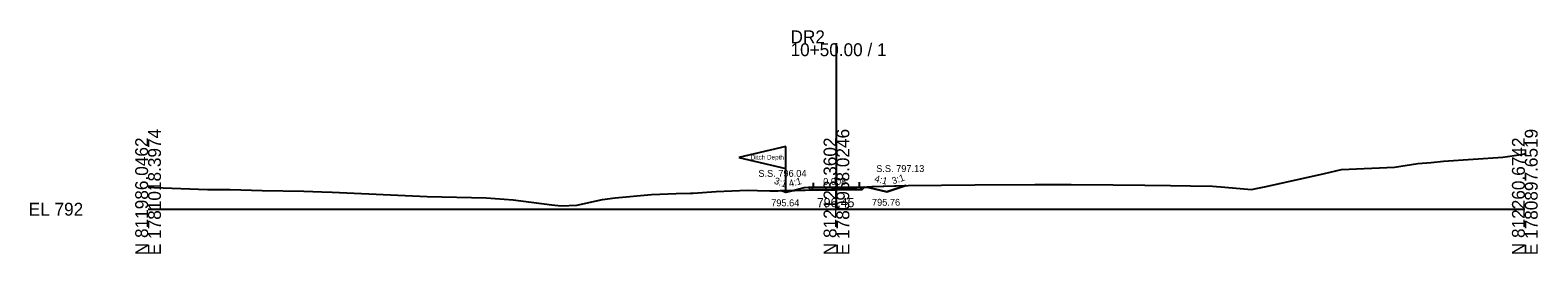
# Model space of a CAD drawing. Extents: x -26 to 303, y -10 to 2560.
# Drawn here: x -25.7 to 302.8, y 990.3 to 1038.9 of the extents above; entities that cross this region are included whole.
import ezdxf

# ---------------------------------------------------------------- set-up
doc = ezdxf.new("R2010")
doc.units = 0
for name, color, linetype in [('Exist Cross Section Cell', 7, 'Continuous'), ('Exist XS Center Line Elevation Label', 7, 'Continuous'), ('Exist XS Ground Line', 7, 'Continuous'), ('Prop XS Ditch Slope Text', 7, 'Continuous'), ('Prop XS Ditch Standard Text', 7, 'Continuous'), ('Prop XS Dump Level', 7, 'Continuous'), ('Prop XS Earthwork Shape', 7, 'Continuous'), ('Prop XS EOT Tick Mark', 7, 'Continuous'), ('Prop XS Finish Grade', 7, 'Continuous'), ('Prop XS Finish Grade Earthwork', 7, 'Continuous'), ('Prop XS Finish Grade Pavement', 7, 'Continuous'), ('Prop XS Pvmt Edge Slope', 7, 'Continuous'), ('Prop XS SE Text', 7, 'Continuous'), ('Prop XS Side Slope Text', 7, 'Continuous'), ('Prop XS SS Elevation Text', 7, 'Continuous'), ('Prop XS Subgrade Earthwork', 7, 'Continuous')]:
    doc.layers.add(name, color=color, linetype=linetype)

msp = doc.modelspace()

# ---------------------------------------------------------------- linework, layer by layer
at = {"layer": 'Exist Cross Section Cell'}
for p, q in [((150, 1000), (150, 1036.1)), ((0, 1000), (150, 1000)), ((150, 1000), (300, 1000))]:
    msp.add_line(p, q, dxfattribs=at)
at = {"layer": 'Exist XS Ground Line'}
for p, q in [((295.24, 1011.36), (299.23, 1011.92)), ((299.23, 1011.92), (299.9, 1012.03)), ((299.9, 1012.03), (300, 1012.02)), ((256.32, 1007.76), (260.06, 1008.68)), ((260.06, 1008.68), (271.58, 1009.14)), ((271.58, 1009.14), (276.71, 1009.97)), ((276.71, 1009.97), (279.63, 1010.17)), ((279.63, 1010.17), (282.28, 1010.46)), ((282.28, 1010.46), (295.24, 1011.36)), ((180.14, 1005.29), (193.25, 1005.41)), ((193.25, 1005.41), (201.12, 1005.37)), ((201.12, 1005.37), (210.33, 1005.28)), ((243.61, 1004.98), (256.32, 1007.76)), ((0, 1004.78), (1.33, 1004.74)), ((1.33, 1004.74), (12.97, 1004.32)), ((12.97, 1004.32), (17.89, 1004.3)), ((17.89, 1004.3), (24.89, 1004.11)), ((24.89, 1004.11), (33.94, 1003.93)), ((33.94, 1003.93), (37.84, 1003.81)), ((37.84, 1003.81), (40.09, 1003.72)), ((40.09, 1003.72), (60.8, 1002.74)), ((60.8, 1002.74), (73.66, 1002.5)), ((73.66, 1002.5), (79.55, 1002.01)), ((93.4, 1000.92), (99, 1002.14)), ((99, 1002.14), (101.76, 1002.48)), ((101.76, 1002.48), (109.69, 1003.19)), ((109.69, 1003.19), (115.07, 1003.39)), ((115.07, 1003.39), (118.23, 1003.46)), ((118.23, 1003.46), (118.78, 1003.49)), ((118.78, 1003.49), (123.78, 1003.87)), ((123.78, 1003.87), (130.64, 1004.12)), ((130.64, 1004.12), (132.77, 1004.05)), ((132.77, 1004.05), (135.48, 1004.03)), ((135.48, 1004.03), (137.31, 1004.03)), ((137.31, 1004.03), (146.09, 1004.22)), ((146.09, 1004.22), (146.93, 1004.24)), ((146.93, 1004.24), (147.28, 1004.26)), ((147.28, 1004.26), (147.85, 1004.31)), ((147.85, 1004.31), (150, 1004.45)), ((150, 1004.45), (157.69, 1004.94)), ((157.69, 1004.94), (165.64, 1005.15)), ((165.64, 1005.15), (180.14, 1005.29)), ((210.33, 1005.28), (217.23, 1005.23)), ((217.23, 1005.23), (222.81, 1005.15)), ((222.81, 1005.15), (227.17, 1005.06)), ((227.17, 1005.06), (231.93, 1005.04)), ((231.93, 1005.04), (234.65, 1004.81)), ((234.65, 1004.81), (240.43, 1004.28)), ((240.43, 1004.28), (241.47, 1004.5)), ((241.47, 1004.5), (243.61, 1004.98)), ((79.55, 1002.01), (88, 1000.95)), ((88, 1000.95), (89.99, 1000.71)), ((89.99, 1000.71), (93.4, 1000.92))]:
    msp.add_line(p, q, dxfattribs=at)
at = {"layer": 'Prop XS Dump Level'}
for p, q in [((139, 1013.64), (128.7, 1011.24)), ((139, 1008.84), (139, 1013.64)), ((128.7, 1011.24), (139, 1008.84)), ((139, 1003.64), (139, 1008.84)), ((145, 1004.78), (150, 1004.82)), ((150, 1004.82), (155, 1004.86))]:
    msp.add_line(p, q, dxfattribs=at)
at = {"layer": 'Prop XS Earthwork Shape'}
for points in [[(137.79, 1004.04), (140.87, 1004.11), (139, 1003.64)], [(140.87, 1004.11), (144.41, 1004.19), (143.9, 1004.7), (143, 1004.64)], [(144.41, 1004.19), (146.09, 1004.22), (146.93, 1004.24), (147.28, 1004.26), (147.85, 1004.31), (150, 1004.45), (157.69, 1004.94), (165.13, 1005.13), (161, 1003.76), (157, 1004.76), (156.1, 1004.8), (155.58, 1004.28), (150, 1004.23)]]:
    msp.add_lwpolyline(points, close=True, dxfattribs=at)
at = {"layer": 'Prop XS EOT Tick Mark'}
for p, q in [((145, 1004.78), (145, 1005.78)), ((155, 1004.86), (155, 1005.86))]:
    msp.add_line(p, q, dxfattribs=at)
at = {"layer": 'Prop XS Finish Grade'}
for p, q in [((145, 1004.78), (143.9, 1004.7)), ((155, 1004.86), (156.1, 1004.8))]:
    msp.add_line(p, q, dxfattribs=at)
at = {"layer": 'Prop XS Finish Grade Earthwork'}
for p, q in [((139, 1003.64), (137.79, 1004.04)), ((143, 1004.64), (139, 1003.64)), ((143.9, 1004.7), (143, 1004.64)), ((156.1, 1004.8), (157, 1004.76)), ((157, 1004.76), (161, 1003.76)), ((161, 1003.76), (165.13, 1005.13))]:
    msp.add_line(p, q, dxfattribs=at)
at = {"layer": 'Prop XS Finish Grade Pavement'}
for p, q in [((145, 1004.78), (150, 1004.82)), ((150, 1004.82), (155, 1004.86))]:
    msp.add_line(p, q, dxfattribs=at)
at = {"layer": 'Prop XS Pvmt Edge Slope'}
for p, q in [((145, 1004.78), (144.41, 1004.19)), ((155, 1004.86), (155.58, 1004.28))]:
    msp.add_line(p, q, dxfattribs=at)
at = {"layer": 'Prop XS Subgrade Earthwork'}
for p, q in [((144.41, 1004.19), (143.9, 1004.7)), ((144.41, 1004.19), (150, 1004.23)), ((150, 1004.23), (155.58, 1004.28)), ((155.58, 1004.28), (156.1, 1004.8))]:
    msp.add_line(p, q, dxfattribs=at)

# ---------------------------------------------------------------- texts
at = {"layer": 'Exist Cross Section Cell'}
for s, p in [('DR2', (140, 1036.1)), ('10+50.00 / 1', (140, 1033.3)), ('EL 792', (-26, 998.6))]:
    msp.add_text(s, height=2.8, dxfattribs=at).set_placement(p)
for s, p in [('N 811986.0462', (0, 990)), ('E 1781018.3974', (2.8, 990)), ('N 812123.3602', (150, 990)), ('E 1780958.0246', (152.8, 990)), ('N 812260.6742', (300, 990)), ('E 1780897.6519', (302.8, 990))]:
    msp.add_text(s, height=2.8, rotation=90, dxfattribs=at).set_placement(p)
at = {"layer": 'Exist XS Center Line Elevation Label'}
msp.add_text('796.45', height=2, dxfattribs=at).set_placement((145.74, 1000.45))
at = {"layer": 'Prop XS Ditch Slope Text'}
for rotation, p in [(14.0362, (139.82, 1004.82)), (345.9638, (158.19, 1006.01))]:
    msp.add_text('4:1', height=1.5, rotation=rotation, dxfattribs=at).set_placement(p)
at = {"layer": 'Prop XS Ditch Standard Text'}
for s, p in [('795.64', (135.78, 1000.64)), ('795.76', (157.74, 1000.76))]:
    msp.add_text(s, height=1.5, dxfattribs=at).set_placement(p)
at = {"layer": 'Prop XS Dump Level'}
for s, height, p in [('Ditch Depth', 1, (131.34, 1010.81)), ('Case1', 0.04, (143, 1004.6)), ('Case1', 0.04, (157, 1004.72))]:
    msp.add_text(s, height=height, dxfattribs=at).set_placement(p)
at = {"layer": 'Prop XS SE Text'}
msp.add_text('0.008', height=1.5, rotation=0.4746, dxfattribs=at).set_placement((147.12, 1005.28))
at = {"layer": 'Prop XS Side Slope Text'}
for rotation, p in [(341.5651, (136.28, 1005.59)), (18.4349, (162.34, 1005.4))]:
    msp.add_text('3:1', height=1.5, rotation=rotation, dxfattribs=at).set_placement(p)
at = {"layer": 'Prop XS SS Elevation Text'}
for s, p in [('S.S. 797.13', (158.66, 1008.1)), ('S.S. 796.04', (132.99, 1007.05))]:
    msp.add_text(s, height=1.5, dxfattribs=at).set_placement(p)

doc.saveas('drawing.dxf')
